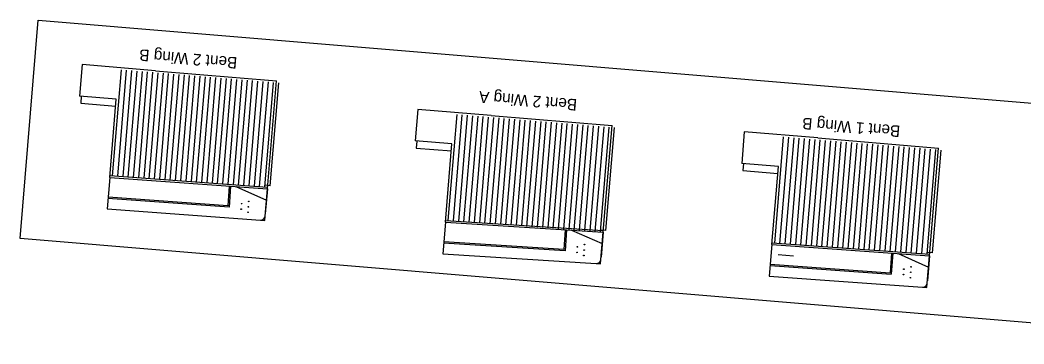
# Model space of a CAD drawing. Extents: x 1313815 to 1314857, y 2089008 to 2089414.
# Drawn here: x 1314563.7 to 1314659, y 2089292.2 to 2089322.9 of the extents above; entities that cross this region are included whole.
import ezdxf

# ---------------------------------------------------------------- set-up
doc = ezdxf.new("R2010")
doc.units = 0
for name, color, linetype in [('B-Gen-Hidden', 7, 'Continuous'), ('B-Gen-Rebar', 7, 'Continuous'), ('B-Gen-Viewport', 7, 'Continuous'), ('B-Sub-Abutment Cap (Hidden)', 7, 'Continuous'), ('B-Sub-Wingwall', 7, 'Continuous'), ('B-Super-Parapet', 7, 'Continuous')]:
    doc.layers.add(name, color=color, linetype=linetype)

msp = doc.modelspace()

# ---------------------------------------------------------------- linework, layer by layer
at = {"layer": 'B-Gen-Hidden'}
for p, q in [((1314587.451, 2089307.215), (1314588.266, 2089316.974)), ((1314619.306, 2089302.971), (1314620.121, 2089312.73)), ((1314650.294, 2089300.842), (1314651.109, 2089310.601)), ((1314572.228, 2089308.17), (1314587.189, 2089307.076)), ((1314572.214, 2089308.004), (1314587.175, 2089306.909)), ((1314587.451, 2089307.215), (1314586.953, 2089307.257)), ((1314583.559, 2089307.174), (1314583.423, 2089305.304)), ((1314583.684, 2089307.165), (1314583.538, 2089305.17)), ((1314584.183, 2089307.128), (1314587.085, 2089305.83)), ((1314583.538, 2089305.17), (1314572.048, 2089306.011)), ((1314583.423, 2089305.304), (1314572.058, 2089306.135)), ((1314586.516, 2089303.95), (1314586.925, 2089303.92)), ((1314586.925, 2089303.92), (1314586.96, 2089304.331)), ((1314604.069, 2089303.76), (1314619.042, 2089302.809)), ((1314604.083, 2089303.926), (1314619.056, 2089302.975)), ((1314615.424, 2089303.039), (1314615.305, 2089301.168)), ((1314615.548, 2089303.031), (1314615.421, 2089301.035)), ((1314616.047, 2089302.999), (1314618.952, 2089301.729)), ((1314619.306, 2089302.971), (1314618.808, 2089303.013)), ((1314615.421, 2089301.035), (1314603.903, 2089301.766)), ((1314615.305, 2089301.168), (1314603.913, 2089301.891)), ((1314635.057, 2089301.631), (1314650.02, 2089300.559)), ((1314635.071, 2089301.797), (1314650.034, 2089300.725)), ((1314635.638, 2089300.696), (1314637.109, 2089300.573)), ((1314646.406, 2089300.818), (1314646.272, 2089298.948)), ((1314646.53, 2089300.809), (1314646.387, 2089298.814)), ((1314647.027, 2089300.773), (1314649.93, 2089299.479)), ((1314650.294, 2089300.842), (1314649.796, 2089300.884)), ((1314618.383, 2089299.845), (1314618.792, 2089299.819)), ((1314618.792, 2089299.819), (1314618.826, 2089300.226)), ((1314634.891, 2089299.638), (1314646.387, 2089298.814)), ((1314634.901, 2089299.763), (1314646.272, 2089298.948)), ((1314649.77, 2089297.569), (1314649.805, 2089297.982)), ((1314649.361, 2089297.599), (1314649.77, 2089297.569))]:
    msp.add_line(p, q, dxfattribs=at)
at = {"layer": 'B-Gen-Rebar'}
for p, q in [((1314572.477, 2089308.152), (1314573.318, 2089318.221)), ((1314572.976, 2089308.115), (1314573.816, 2089318.18)), ((1314573.475, 2089308.079), (1314574.314, 2089318.138)), ((1314573.973, 2089308.042), (1314574.813, 2089318.097)), ((1314574.472, 2089308.006), (1314575.311, 2089318.055)), ((1314574.971, 2089307.969), (1314575.809, 2089318.014)), ((1314575.469, 2089307.933), (1314576.307, 2089317.972)), ((1314575.968, 2089307.896), (1314576.806, 2089317.93)), ((1314576.467, 2089307.86), (1314577.304, 2089317.889)), ((1314576.966, 2089307.823), (1314577.802, 2089317.847)), ((1314577.464, 2089307.787), (1314578.3, 2089317.806)), ((1314577.963, 2089307.75), (1314578.799, 2089317.764)), ((1314578.462, 2089307.714), (1314579.297, 2089317.722)), ((1314578.96, 2089307.677), (1314579.795, 2089317.681)), ((1314579.459, 2089307.641), (1314580.294, 2089317.639)), ((1314579.958, 2089307.604), (1314580.792, 2089317.598)), ((1314580.456, 2089307.568), (1314581.29, 2089317.556)), ((1314580.955, 2089307.532), (1314581.788, 2089317.514)), ((1314581.454, 2089307.495), (1314582.287, 2089317.473)), ((1314581.952, 2089307.459), (1314582.785, 2089317.431)), ((1314582.451, 2089307.422), (1314583.283, 2089317.39)), ((1314582.95, 2089307.386), (1314583.781, 2089317.348)), ((1314583.449, 2089307.349), (1314584.28, 2089317.306)), ((1314583.947, 2089307.313), (1314584.778, 2089317.265)), ((1314584.446, 2089307.276), (1314585.276, 2089317.223)), ((1314584.945, 2089307.24), (1314585.775, 2089317.182)), ((1314585.443, 2089307.203), (1314586.273, 2089317.14)), ((1314585.942, 2089307.167), (1314586.771, 2089317.098)), ((1314586.441, 2089307.13), (1314587.269, 2089317.057)), ((1314586.939, 2089307.094), (1314587.768, 2089317.015)), ((1314604.332, 2089303.908), (1314605.173, 2089313.977)), ((1314604.831, 2089303.871), (1314605.671, 2089313.936)), ((1314605.33, 2089303.835), (1314606.169, 2089313.894)), ((1314605.828, 2089303.798), (1314606.668, 2089313.853)), ((1314606.327, 2089303.762), (1314607.166, 2089313.811)), ((1314606.826, 2089303.725), (1314607.664, 2089313.77)), ((1314607.324, 2089303.689), (1314608.162, 2089313.728)), ((1314607.823, 2089303.652), (1314608.661, 2089313.686)), ((1314608.322, 2089303.616), (1314609.159, 2089313.645)), ((1314608.821, 2089303.579), (1314609.657, 2089313.603)), ((1314609.319, 2089303.543), (1314610.156, 2089313.562)), ((1314609.818, 2089303.506), (1314610.654, 2089313.52)), ((1314610.317, 2089303.47), (1314611.152, 2089313.478)), ((1314610.815, 2089303.433), (1314611.65, 2089313.437)), ((1314611.314, 2089303.397), (1314612.149, 2089313.395)), ((1314611.813, 2089303.36), (1314612.647, 2089313.354)), ((1314612.311, 2089303.324), (1314613.145, 2089313.312)), ((1314612.81, 2089303.288), (1314613.643, 2089313.27)), ((1314613.309, 2089303.251), (1314614.142, 2089313.229)), ((1314613.807, 2089303.215), (1314614.64, 2089313.187)), ((1314614.306, 2089303.178), (1314615.138, 2089313.146)), ((1314614.805, 2089303.142), (1314615.636, 2089313.104)), ((1314615.304, 2089303.105), (1314616.135, 2089313.062)), ((1314615.802, 2089303.069), (1314616.633, 2089313.021)), ((1314616.301, 2089303.032), (1314617.131, 2089312.979)), ((1314616.8, 2089302.996), (1314617.63, 2089312.938)), ((1314617.298, 2089302.959), (1314618.128, 2089312.896)), ((1314617.797, 2089302.923), (1314618.626, 2089312.855)), ((1314618.296, 2089302.886), (1314619.124, 2089312.813)), ((1314618.794, 2089302.85), (1314619.623, 2089312.771)), ((1314635.32, 2089301.779), (1314636.161, 2089311.849)), ((1314635.819, 2089301.743), (1314636.659, 2089311.807)), ((1314636.318, 2089301.706), (1314637.158, 2089311.766)), ((1314636.816, 2089301.67), (1314637.656, 2089311.724)), ((1314637.315, 2089301.633), (1314638.154, 2089311.683)), ((1314637.814, 2089301.597), (1314638.652, 2089311.641)), ((1314638.313, 2089301.56), (1314639.151, 2089311.599)), ((1314638.811, 2089301.524), (1314639.649, 2089311.558)), ((1314639.31, 2089301.487), (1314640.147, 2089311.516)), ((1314639.809, 2089301.451), (1314640.645, 2089311.475)), ((1314640.307, 2089301.414), (1314641.144, 2089311.433)), ((1314640.806, 2089301.378), (1314641.642, 2089311.391)), ((1314641.305, 2089301.341), (1314642.14, 2089311.35)), ((1314641.803, 2089301.305), (1314642.638, 2089311.308)), ((1314642.302, 2089301.268), (1314643.137, 2089311.267)), ((1314642.801, 2089301.232), (1314643.635, 2089311.225)), ((1314643.3, 2089301.195), (1314644.133, 2089311.183)), ((1314643.798, 2089301.159), (1314644.632, 2089311.142)), ((1314644.297, 2089301.122), (1314645.13, 2089311.1)), ((1314644.796, 2089301.086), (1314645.628, 2089311.059)), ((1314645.294, 2089301.049), (1314646.126, 2089311.017)), ((1314645.793, 2089301.013), (1314646.625, 2089310.975)), ((1314646.292, 2089300.977), (1314647.123, 2089310.934)), ((1314646.79, 2089300.94), (1314647.621, 2089310.892)), ((1314647.289, 2089300.904), (1314648.119, 2089310.851)), ((1314647.788, 2089300.867), (1314648.618, 2089310.809)), ((1314648.286, 2089300.831), (1314649.116, 2089310.767)), ((1314648.785, 2089300.794), (1314649.614, 2089310.726)), ((1314649.284, 2089300.758), (1314650.112, 2089310.684)), ((1314649.783, 2089300.721), (1314650.611, 2089310.643))]:
    msp.add_line(p, q, dxfattribs=at)
for centre, radius in [((1314584.725, 2089305.514), 0.0313), ((1314585.406, 2089305.733), 0.0312), ((1314584.693, 2089304.993), 0.0313), ((1314585.342, 2089304.692), 0.0313), ((1314585.374, 2089305.213), 0.0313), ((1314617.273, 2089301.633), 0.0312), ((1314616.56, 2089300.893), 0.0313), ((1314616.592, 2089301.413), 0.0313), ((1314617.209, 2089300.592), 0.0313), ((1314617.241, 2089301.112), 0.0313), ((1314647.55, 2089298.786), 0.0313), ((1314647.582, 2089299.306), 0.0313), ((1314648.231, 2089299.006), 0.0313), ((1314648.263, 2089299.526), 0.0312), ((1314648.199, 2089298.485), 0.0313)]:
    msp.add_circle(centre, radius, dxfattribs=at)
at = {"layer": 'B-Gen-Viewport'}
msp.add_lwpolyline([(1314683.41, 2089292.211), (1314563.704, 2089302.203), (1314565.434, 2089322.927), (1314685.14, 2089312.935)], close=True, dxfattribs=at)
at = {"layer": 'B-Sub-Wingwall'}
for p, q in [((1314569.595, 2089318.699), (1314569.345, 2089315.71)), ((1314576.57, 2089318.117), (1314569.595, 2089318.699)), ((1314576.57, 2089318.117), (1314588.031, 2089317.161)), ((1314587.175, 2089306.909), (1314588.031, 2089317.161)), ((1314572.833, 2089315.419), (1314569.345, 2089315.71)), ((1314569.511, 2089315.696), (1314569.456, 2089315.032)), ((1314569.456, 2089315.032), (1314572.778, 2089314.754)), ((1314572.214, 2089308.004), (1314572.833, 2089315.419)), ((1314601.45, 2089314.456), (1314601.2, 2089311.466)), ((1314608.425, 2089313.873), (1314601.45, 2089314.456)), ((1314608.425, 2089313.873), (1314619.886, 2089312.917)), ((1314619.042, 2089302.809), (1314619.886, 2089312.917)), ((1314632.438, 2089312.327), (1314632.188, 2089309.337)), ((1314639.414, 2089311.745), (1314632.438, 2089312.327)), ((1314604.688, 2089311.175), (1314601.2, 2089311.466)), ((1314601.366, 2089311.452), (1314601.311, 2089310.788)), ((1314604.069, 2089303.76), (1314604.688, 2089311.175)), ((1314639.414, 2089311.745), (1314650.874, 2089310.788)), ((1314601.311, 2089310.788), (1314604.633, 2089310.51)), ((1314650.02, 2089300.559), (1314650.874, 2089310.788)), ((1314635.676, 2089309.046), (1314632.188, 2089309.337)), ((1314632.354, 2089309.323), (1314632.299, 2089308.659)), ((1314632.299, 2089308.659), (1314635.621, 2089308.382)), ((1314635.057, 2089301.631), (1314635.676, 2089309.046))]:
    msp.add_line(p, q, dxfattribs=at)
for centre in [(1314586.544, 2089304.366), (1314618.411, 2089300.261), (1314649.389, 2089298.014)]:
    msp.add_arc(centre, 0.417, 266.10988, 355.22842, dxfattribs=at)
at = {"layer": 'B-Super-Parapet'}
for p, q in [((1314572.214, 2089308.004), (1314571.964, 2089305.014)), ((1314586.96, 2089304.331), (1314587.175, 2089306.909)), ((1314587.175, 2089306.909), (1314586.977, 2089304.542)), ((1314571.964, 2089305.014), (1314586.516, 2089303.95)), ((1314604.069, 2089303.76), (1314603.82, 2089300.77)), ((1314618.826, 2089300.226), (1314619.042, 2089302.809)), ((1314619.042, 2089302.809), (1314618.844, 2089300.441)), ((1314635.057, 2089301.631), (1314634.808, 2089298.642)), ((1314603.82, 2089300.77), (1314618.387, 2089299.845)), ((1314649.805, 2089297.982), (1314650.02, 2089300.559)), ((1314650.02, 2089300.559), (1314649.822, 2089298.191)), ((1314650.02, 2089300.559), (1314649.93, 2089299.479)), ((1314634.808, 2089298.642), (1314649.361, 2089297.599))]:
    msp.add_line(p, q, dxfattribs=at)

# ---------------------------------------------------------------- texts
at = {"layer": 'B-Sub-Abutment Cap (Hidden)'}
for s, p in [('Bent 2 Wing B', (1314584.349, 2089319.395)), ('Bent 2 Wing A', (1314616.6, 2089315.417)), ('Bent 1 Wing B', (1314647.267, 2089312.905))]:
    msp.add_text(s, height=1.09106, rotation=175.22842, dxfattribs=at).set_placement(p)

doc.saveas('drawing.dxf')
